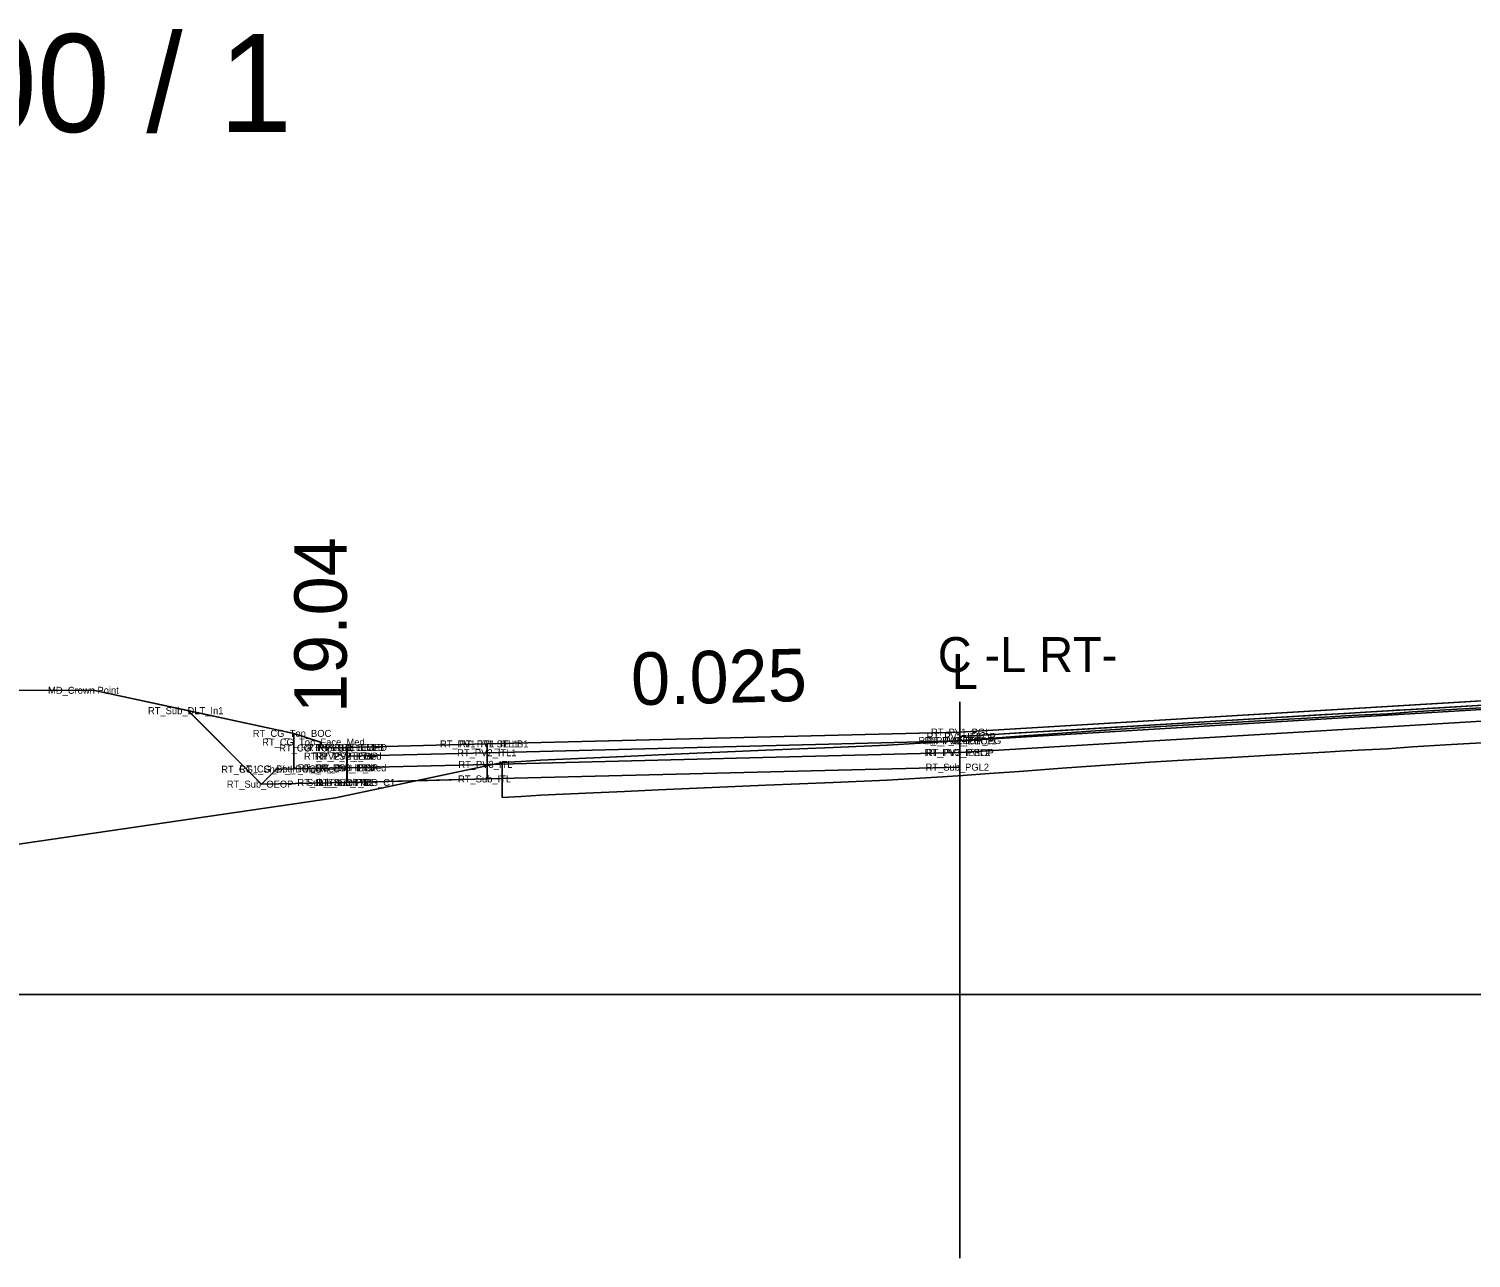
# Model space of a CAD drawing. Extents: x 2177029 to 2201446, y 59897 to 78390.
# Drawn here: x 2199246.14 to 2199287.33, y 67899.77 to 67934.89 of the extents above; entities that cross this region are included whole.
import ezdxf

# ---------------------------------------------------------------- set-up
doc = ezdxf.new("R2010")
doc.units = 0
for name, color, linetype in [('Exist CMT Pavement', 7, 'Continuous'), ('Exist Cross Section Cell', 7, 'Continuous'), ('Exist PHM Roadway Shape', 7, 'Continuous'), ('Exist XS Ground Line', 7, 'Continuous'), ('Old_Level_11', 7, 'Continuous'), ('Prop CMT Conc Surface', 7, 'Continuous'), ('Prop CMT Concrete Structures', 7, 'Continuous'), ('Prop CMT Guardrail Graphics', 7, 'Continuous'), ('Prop CMT Pvmt Course 1 CG', 7, 'Continuous'), ('Prop CMT Pvmt Course 2', 7, 'Continuous'), ('Prop CMT Pvmt Course 2 CG', 7, 'Continuous'), ('Prop CMT Pvmt Course 3', 7, 'Continuous'), ('Prop CMT Pvmt Course 4', 7, 'Continuous'), ('Prop CMT Pvmt Surface', 7, 'Continuous'), ('Prop CMT Pvmt Wedge Surface 1', 7, 'Continuous'), ('Prop CMT Slope Grass', 7, 'Continuous'), ('Prop CMT Subgrade Earthwork', 7, 'Continuous'), ('Prop CMT Top Wall Envelope', 7, 'Continuous'), ('Prop Hatching', 7, 'Continuous'), ('Prop Horizontal Alignment', 7, 'Continuous'), ('Prop Retaining Wall', 7, 'Continuous'), ('Prop Terminator CELL', 7, 'Continuous'), ('Prop XS Side Slope Text', 7, 'Continuous'), ('Scratch_Level_0', 7, 'Continuous'), ('Scratch_Level_9', 7, 'Continuous')]:
    doc.layers.add(name, color=color, linetype=linetype)

msp = doc.modelspace()

# ---------------------------------------------------------------- linework, layer by layer
at = {"layer": 'Exist CMT Pavement'}
msp.add_line((2199272.732, 67899.774), (2199272.732, 67915.668), dxfattribs=at)
at = {"layer": 'Exist Cross Section Cell'}
msp.add_line((2199242.732, 67907.31), (2199442.732, 67907.31), dxfattribs=at)
at = {"layer": 'Exist XS Ground Line'}
msp.add_lwpolyline([(2199245.978, 67911.615), (2199254.899, 67912.928), (2199259.121, 67913.821), (2199259.66, 67913.931), (2199260.197, 67913.965), (2199260.752, 67913.997), (2199262.262, 67914.066), (2199263.153, 67914.105), (2199264.118, 67914.149), (2199265.653, 67914.22), (2199267.191, 67914.285), (2199268.153, 67914.325), (2199269.113, 67914.364), (2199270.653, 67914.429), (2199271.593, 67914.489), (2199272.235, 67914.527), (2199272.812, 67914.566), (2199273.569, 67914.62), (2199274.423, 67914.681), (2199275.653, 67914.769), (2199276.606, 67914.836), (2199278.153, 67914.947), (2199279.105, 67915.002), (2199280.653, 67915.09), (2199281.602, 67915.144), (2199283.153, 67915.232), (2199283.745, 67915.263), (2199284.303, 67915.293), (2199284.942, 67915.327), (2199285.653, 67915.382), (2199286.598, 67915.436), (2199288.153, 67915.523)], dxfattribs=at)
at = {"layer": 'Prop CMT Conc Surface'}
for points in [[(2199272.732, 67914.676), (2199307.213, 67916.745)], [(2199272.732, 67914.801), (2199272.732, 67914.551), (2199272.732, 67914.551), (2199272.732, 67914.676)]]:
    msp.add_lwpolyline(points, dxfattribs=at)
at = {"layer": 'Prop CMT Concrete Structures'}
for p, q in [((2199272.732, 67914.801), (2199308.732, 67916.961)), ((2199272.732, 67914.801), (2199259.233, 67914.464)), ((2199255.223, 67914.363), (2199255.222, 67914.363)), ((2199255.232, 67914.364), (2199255.223, 67914.363)), ((2199259.233, 67914.464), (2199259.232, 67914.464))]:
    msp.add_line(p, q, dxfattribs=at)
at = {"layer": 'Prop CMT Guardrail Graphics'}
for points in [[(2199272.732, 67914.218), (2199308.732, 67916.378)], [(2199272.732, 67914.801), (2199272.732, 67914.218)]]:
    msp.add_lwpolyline(points, dxfattribs=at)
at = {"layer": 'Prop CMT Pvmt Course 1 CG'}
for points in [[(2199255.232, 67913.78), (2199259.232, 67913.88)], [(2199255.232, 67913.364), (2199255.232, 67913.78)], [(2199259.232, 67913.88), (2199259.232, 67913.464)], [(2199259.232, 67913.464), (2199255.232, 67913.364)]]:
    msp.add_lwpolyline(points, dxfattribs=at)
at = {"layer": 'Prop CMT Pvmt Course 2'}
for points in [[(2199272.732, 67914.218), (2199259.232, 67913.88)], [(2199272.732, 67913.801), (2199272.732, 67914.218)], [(2199255.232, 67913.78), (2199255.222, 67913.78)], [(2199255.222, 67913.78), (2199255.222, 67913.363)], [(2199255.232, 67913.364), (2199255.232, 67913.78)], [(2199259.232, 67913.88), (2199259.232, 67913.464)], [(2199259.232, 67913.464), (2199272.732, 67913.801)], [(2199255.222, 67913.363), (2199255.232, 67913.364)]]:
    msp.add_lwpolyline(points, dxfattribs=at)
at = {"layer": 'Prop CMT Pvmt Course 2 CG'}
for points in [[(2199272.732, 67914.801), (2199308.732, 67916.961)], [(2199307.213, 67916.745), (2199272.732, 67914.676)], [(2199272.732, 67914.801), (2199259.232, 67914.464)], [(2199259.232, 67914.214), (2199272.732, 67914.551)], [(2199272.732, 67914.551), (2199272.732, 67914.801)], [(2199272.732, 67914.551), (2199272.732, 67914.801)], [(2199272.732, 67914.676), (2199272.732, 67914.551), (2199272.732, 67914.551)], [(2199255.232, 67914.364), (2199255.222, 67914.363)], [(2199255.222, 67914.363), (2199255.222, 67914.113)], [(2199255.222, 67914.113), (2199255.232, 67914.114)], [(2199255.232, 67914.114), (2199255.232, 67914.364)], [(2199259.232, 67914.464), (2199259.232, 67914.214)]]:
    msp.add_lwpolyline(points, dxfattribs=at)
at = {"layer": 'Prop CMT Pvmt Course 3'}
msp.add_line((2199272.732, 67914.561), (2199272.732, 67913.801), dxfattribs=at)
for points in [[(2199250.687, 67915.414), (2199252.786, 67913.315)], [(2199259.232, 67913.464), (2199272.732, 67913.801)], [(2199255.222, 67913.363), (2199252.786, 67913.315)], [(2199255.232, 67913.364), (2199255.222, 67913.363)], [(2199255.222, 67913.363), (2199255.222, 67913.363)], [(2199259.232, 67913.464), (2199255.232, 67913.364)]]:
    msp.add_lwpolyline(points, dxfattribs=at)
at = {"layer": 'Prop CMT Pvmt Course 4'}
msp.add_lwpolyline([(2199259.232, 67914.464), (2199255.232, 67914.364)], dxfattribs=at)
at = {"layer": 'Prop CMT Pvmt Surface'}
for points in [[(2199272.732, 67914.676), (2199272.812, 67914.681), (2199273.569, 67914.727), (2199274.423, 67914.778), (2199275.653, 67914.852), (2199276.606, 67914.909), (2199278.153, 67915.002), (2199279.105, 67915.059), (2199280.653, 67915.152), (2199281.602, 67915.209), (2199283.153, 67915.302), (2199283.745, 67915.337), (2199284.303, 67915.371), (2199284.942, 67915.409), (2199285.202, 67915.425), (2199285.423, 67915.438), (2199285.653, 67915.452), (2199286.598, 67915.508), (2199288.153, 67915.602)], [(2199288.153, 67915.523), (2199286.598, 67915.436), (2199285.653, 67915.382), (2199285.423, 67915.364), (2199285.202, 67915.347), (2199284.942, 67915.327), (2199284.303, 67915.293), (2199283.745, 67915.263), (2199283.153, 67915.232), (2199281.602, 67915.144), (2199280.653, 67915.09), (2199279.105, 67915.002), (2199278.153, 67914.947), (2199276.606, 67914.836), (2199275.653, 67914.769), (2199274.423, 67914.681), (2199273.569, 67914.62), (2199272.812, 67914.566), (2199272.732, 67914.561)], [(2199272.732, 67914.561), (2199272.732, 67914.676)]]:
    msp.add_lwpolyline(points, dxfattribs=at)
at = {"layer": 'Prop CMT Pvmt Wedge Surface 1'}
for p, q in [((2199286.598, 67914.436), (2199288.153, 67914.523)), ((2199279.105, 67914.002), (2199280.653, 67914.09)), ((2199280.653, 67914.09), (2199281.602, 67914.144)), ((2199281.602, 67914.144), (2199283.153, 67914.232)), ((2199283.153, 67914.232), (2199283.745, 67914.263)), ((2199283.745, 67914.263), (2199284.303, 67914.293)), ((2199284.303, 67914.293), (2199284.942, 67914.327)), ((2199284.942, 67914.327), (2199285.653, 67914.382)), ((2199285.653, 67914.382), (2199286.598, 67914.436)), ((2199259.66, 67912.931), (2199259.66, 67913.931)), ((2199273.569, 67913.62), (2199274.423, 67913.681)), ((2199274.423, 67913.681), (2199275.653, 67913.769)), ((2199275.653, 67913.769), (2199276.606, 67913.836)), ((2199276.606, 67913.836), (2199278.153, 67913.947)), ((2199278.153, 67913.947), (2199279.105, 67914.002)), ((2199265.653, 67913.22), (2199267.191, 67913.285)), ((2199267.191, 67913.285), (2199268.153, 67913.325)), ((2199268.153, 67913.325), (2199269.113, 67913.364)), ((2199269.113, 67913.364), (2199270.653, 67913.429)), ((2199270.653, 67913.429), (2199271.593, 67913.489)), ((2199271.593, 67913.489), (2199272.235, 67913.527)), ((2199272.235, 67913.527), (2199272.812, 67913.566)), ((2199272.812, 67913.566), (2199273.569, 67913.62)), ((2199259.66, 67912.931), (2199260.197, 67912.965)), ((2199260.197, 67912.965), (2199260.752, 67912.997)), ((2199260.752, 67912.997), (2199262.262, 67913.066)), ((2199262.262, 67913.066), (2199263.153, 67913.105)), ((2199263.153, 67913.105), (2199264.118, 67913.149)), ((2199264.118, 67913.149), (2199265.653, 67913.22))]:
    msp.add_line(p, q, dxfattribs=at)
at = {"layer": 'Prop CMT Slope Grass'}
for points in [[(2199272.732, 67914.551), (2199259.232, 67914.214)], [(2199272.732, 67914.218), (2199272.732, 67914.551)], [(2199255.232, 67914.114), (2199255.222, 67914.113)], [(2199255.222, 67914.113), (2199255.222, 67913.78)], [(2199255.232, 67913.78), (2199255.232, 67914.114)], [(2199259.232, 67913.88), (2199272.732, 67914.218)], [(2199259.232, 67914.214), (2199259.232, 67913.88)], [(2199255.222, 67913.78), (2199255.232, 67913.78)]]:
    msp.add_lwpolyline(points, dxfattribs=at)
at = {"layer": 'Prop CMT Subgrade Earthwork'}
for points in [[(2199272.732, 67914.551), (2199308.732, 67916.711)], [(2199272.732, 67914.801), (2199272.732, 67914.551)]]:
    msp.add_lwpolyline(points, dxfattribs=at)
at = {"layer": 'Prop Hatching'}
for points in [[(2199242.252, 67915.986), (2199247.982, 67915.995)], [(2199253.712, 67914.765), (2199247.982, 67915.995)]]:
    msp.add_lwpolyline(points, dxfattribs=at)
at = {"layer": 'Prop Horizontal Alignment'}
for points in [[(2199255.222, 67913.78), (2199253.212, 67913.74), (2199252.786, 67913.315)], [(2199255.222, 67913.363), (2199255.222, 67913.78)], [(2199252.786, 67913.315), (2199255.222, 67913.363)]]:
    msp.add_lwpolyline(points, dxfattribs=at)
at = {"layer": 'Prop Retaining Wall'}
msp.add_lwpolyline([(2199255.222, 67914.363), (2199254.471, 67914.348), (2199254.471, 67914.515), (2199253.712, 67914.765)], dxfattribs=at)
at = {"layer": 'Prop Terminator CELL'}
for points in [[(2199255.222, 67914.363), (2199254.471, 67914.348), (2199254.471, 67914.515), (2199253.712, 67914.765)], [(2199253.712, 67914.765), (2199253.712, 67913.75)], [(2199255.222, 67913.78), (2199255.222, 67914.363)], [(2199253.712, 67913.75), (2199255.222, 67913.78)]]:
    msp.add_lwpolyline(points, dxfattribs=at)
at = {"layer": 'Prop XS Side Slope Text'}
msp.add_lwpolyline([(2199308.742, 67916.962), (2199272.732, 67914.801), (2199259.232, 67914.464), (2199255.232, 67914.364), (2199254.471, 67914.348), (2199254.471, 67914.515), (2199253.712, 67914.765), (2199250.686, 67915.415), (2199252.786, 67913.315), (2199255.232, 67913.364), (2199257.194, 67913.413), (2199259.121, 67913.821), (2199259.66, 67913.931), (2199260.197, 67913.965), (2199260.752, 67913.997), (2199262.262, 67914.066), (2199263.153, 67914.105), (2199264.118, 67914.149), (2199265.653, 67914.22), (2199267.191, 67914.285), (2199268.153, 67914.325), (2199269.113, 67914.364), (2199270.653, 67914.429), (2199271.593, 67914.489), (2199272.235, 67914.527), (2199272.732, 67914.561), (2199273.569, 67914.62), (2199274.423, 67914.681), (2199275.653, 67914.769), (2199276.606, 67914.836), (2199278.153, 67914.947), (2199279.105, 67915.002), (2199280.653, 67915.09), (2199281.602, 67915.144), (2199283.153, 67915.232), (2199283.745, 67915.263), (2199284.303, 67915.293), (2199284.942, 67915.327), (2199285.653, 67915.382), (2199286.598, 67915.436), (2199288.153, 67915.523)], dxfattribs=at)
for points in [[(2199254.899, 67912.928), (2199257.194, 67913.413), (2199255.232, 67913.364), (2199252.786, 67913.315), (2199250.686, 67915.415), (2199247.982, 67915.995), (2199244.538, 67915.99), (2199243.159, 67914.611), (2199242.732, 67914.601), (2199242.732, 67911.319), (2199243.394, 67911.193), (2199245.978, 67911.615)], [(2199259.232, 67913.464), (2199257.194, 67913.413), (2199259.121, 67913.821), (2199259.66, 67913.931), (2199260.197, 67913.965), (2199260.752, 67913.997), (2199262.262, 67914.066), (2199263.153, 67914.105), (2199264.118, 67914.149), (2199265.653, 67914.22), (2199267.191, 67914.285), (2199268.153, 67914.325), (2199269.113, 67914.364), (2199270.653, 67914.429), (2199271.593, 67914.489), (2199272.235, 67914.527), (2199272.732, 67914.561), (2199272.732, 67913.801)]]:
    msp.add_lwpolyline(points, close=True, dxfattribs=at)
at = {"layer": 'Scratch_Level_0'}
for points in [[(2199259.232, 67914.214), (2199255.232, 67914.114)], [(2199255.232, 67914.114), (2199255.232, 67913.78)], [(2199259.232, 67913.88), (2199259.232, 67914.214)], [(2199255.232, 67913.78), (2199259.232, 67913.88)]]:
    msp.add_lwpolyline(points, dxfattribs=at)
at = {"layer": 'Scratch_Level_9'}
for points in [[(2199259.232, 67914.464), (2199255.232, 67914.364)], [(2199255.232, 67914.364), (2199255.232, 67914.114)], [(2199255.232, 67914.114), (2199259.232, 67914.214)], [(2199259.232, 67914.214), (2199259.232, 67914.464)]]:
    msp.add_lwpolyline(points, dxfattribs=at)

# ---------------------------------------------------------------- texts
at = {"layer": 'Exist CMT Pavement'}
for s, p in [('C -L RT-', (2199272.099, 67916.516)), ('L', (2199272.502, 67916.035))]:
    msp.add_text(s, height=1, dxfattribs=at).set_placement(p)
at = {"layer": 'Exist Cross Section Cell'}
msp.add_text('37+00.00 / 1', height=2.8, dxfattribs=at).set_placement((2199232.732, 67931.942))
at = {"layer": 'Exist PHM Roadway Shape'}
for s, p in [('MD_Crown Point', (2199246.689, 67915.895)), ('RT_Sub_DLT_In1', (2199249.543, 67915.314)), ('RT_CG_Top_BOC', (2199252.535, 67914.665)), ('RT_CG_Top_Face_Med', (2199252.803, 67914.415)), ('RT_PV1_ITL SE LB1', (2199257.883, 67914.364)), ('RT_PV1_ITL1', (2199258.43, 67914.364)), ('RT_PV_IEEOP_EG', (2199271.546, 67914.46)), ('RT_PV2_IEEOP', (2199271.723, 67914.451)), ('RT_PV1_IEEOP', (2199271.779, 67914.576)), ('RT_PV2_PGL11', (2199271.782, 67914.451)), ('RT_PV1_PGL', (2199271.905, 67914.701)), ('RT_CG_Top_Gut', (2199253.29, 67914.248)), ('RT_PV1_ITL SE LB', (2199253.907, 67914.263)), ('RT_PV2_ITL_med', (2199254, 67914.013)), ('RT_PV1_ITL_MED', (2199254.08, 67914.263)), ('RT_PS2_IEOP', (2199254.315, 67914.014)), ('RT_PV2_PGL', (2199254.348, 67914.014)), ('RT_PS1_IEOP', (2199254.372, 67914.264)), ('RT_PV2_ITL1', (2199258.373, 67914.114)), ('RT_PV3_IEEOP', (2199271.723, 67914.118)), ('RT_PV3_PGL2', (2199271.759, 67914.118)), ('RT_CG1_Shelf_In_Med', (2199251.635, 67913.64)), ('RT_CG_Bot_BOC_Med', (2199252.149, 67913.65)), ('RT_CG_Bot_IE_Med', (2199253.823, 67913.68)), ('RT_PS3_IEOP', (2199254.315, 67913.68)), ('RT_PV3_PGL', (2199254.348, 67913.68)), ('RT_PV3_ITL1', (2199254.363, 67913.68)), ('RT_PV3_ITL', (2199258.406, 67913.78)), ('RT_Sub_PGL2', (2199271.749, 67913.701)), ('RT_Sub_OEOP', (2199251.793, 67913.215)), ('RT_Sub_IEOT_CG_C1', (2199253.809, 67913.263)), ('Sub_Trench_In', (2199254.084, 67913.264)), ('RT_Sub_PGL', (2199254.339, 67913.264)), ('RT_Sub_ITL1', (2199254.354, 67913.263)), ('RT_Sub_ITL', (2199258.397, 67913.364))]:
    msp.add_text(s, height=0.2, dxfattribs=at).set_placement(p)
at = {"layer": 'Old_Level_11'}
msp.add_text('0.025', height=1.5, rotation=1.43, dxfattribs=at).set_placement((2199263.356, 67915.568))
at = {"layer": 'Prop CMT Top Wall Envelope'}
msp.add_text('19.04', height=1.5, rotation=90, dxfattribs=at).set_placement((2199255.221, 67915.348))

doc.saveas('drawing.dxf')
